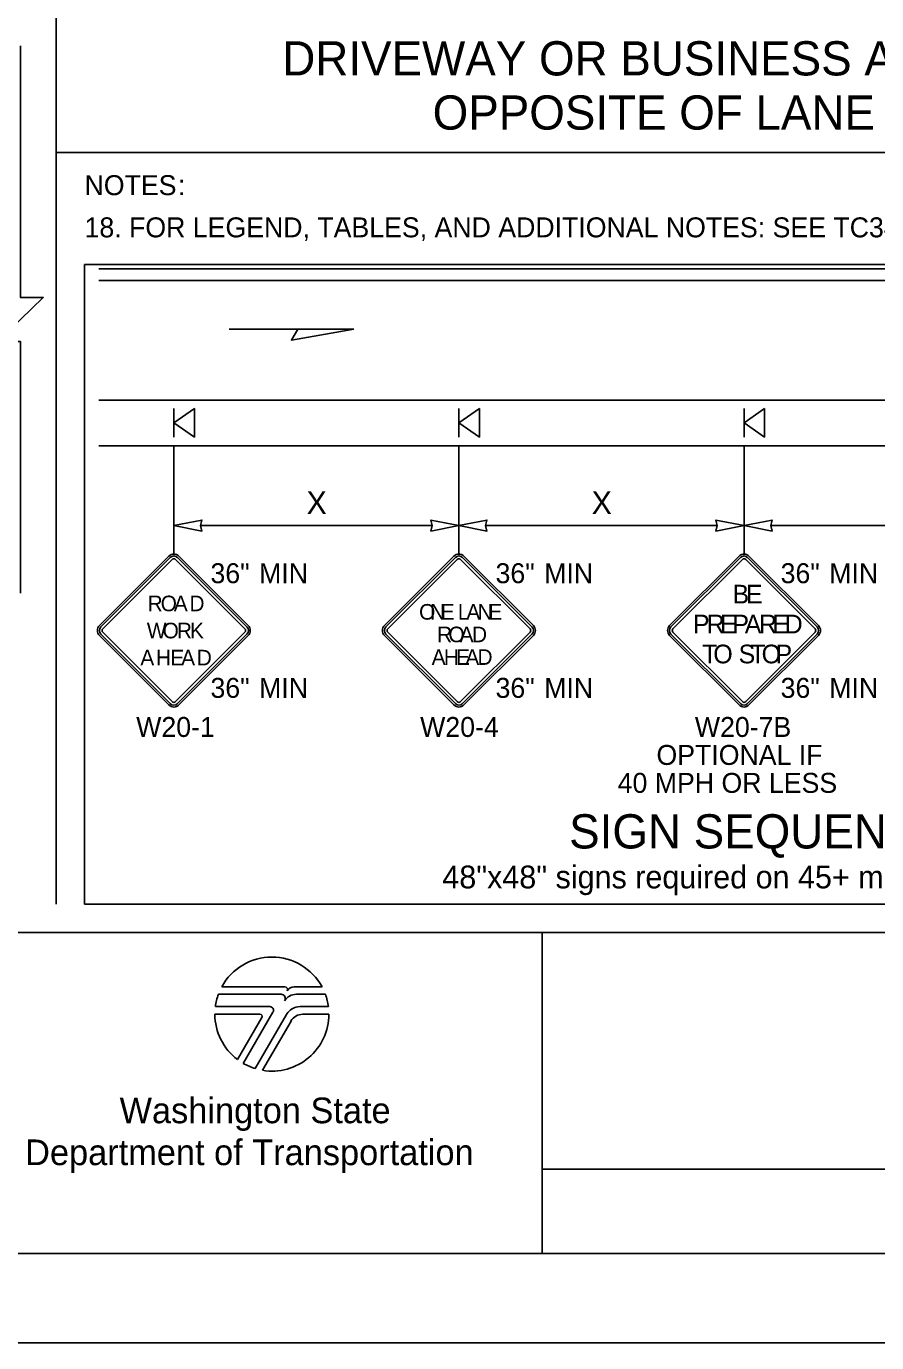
# Model space of a CAD drawing. Extents: x 99979.8 to 100075.7, y 99995 to 100010.7.
# Drawn here: x 100050.396 to 100053.379, y 99999.687 to 100004.304 of the extents above; entities that cross this region are included whole.
import ezdxf

# ---------------------------------------------------------------- set-up
doc = ezdxf.new("R2010")
doc.units = 0
for name, color, linetype in [('RD_ED_ShoulderPavedEdge', 7, 'Continuous'), ('RD_MK_LineDblYellowCenter', 7, 'Continuous'), ('RD_MK_LineEdgeWhite', 7, 'Continuous'), ('SH_DE_DetailHeading2Text', 7, 'Continuous'), ('SH_GI_GeneralNotesBodyText', 7, 'Continuous'), ('SH_GI_PlotLimits', 7, 'Continuous'), ('SH_GI_SheetBorder', 7, 'Continuous'), ('SH_GI_SheetTextInCells', 7, 'Continuous'), ('SH_GI_WSDOTLogo', 7, 'Continuous'), ('TR_SN_ConstructionSigns', 7, 'Continuous'), ('TR_WZ_PortableSignMountBlk-Org', 7, 'Continuous'), ('TR_WZ_WorkZoneDetails', 7, 'Continuous'), ('TR_WZ_WorkZoneTextCurrent', 7, 'Continuous')]:
    doc.layers.add(name, color=color, linetype=linetype)

msp = doc.modelspace()

# ---------------------------------------------------------------- linework, layer by layer
at = {"layer": 'RD_ED_ShoulderPavedEdge'}
msp.add_line((100050.65, 100002.8334), (100055.6, 100002.8334), dxfattribs=at)
at = {"layer": 'RD_MK_LineDblYellowCenter'}
for p, q in [((100050.65, 100003.4534), (100054.9276, 100003.4534)), ((100050.65, 100003.4134), (100054.9776, 100003.4134))]:
    msp.add_line(p, q, dxfattribs=at)
at = {"layer": 'RD_MK_LineEdgeWhite'}
msp.add_line((100050.65, 100002.9934), (100054.9776, 100002.9934), dxfattribs=at)
at = {"layer": 'SH_GI_PlotLimits'}
msp.add_lwpolyline([(100039.0625, 99999.6875), (100056.0625, 99999.6875), (100056.0625, 100010.6875), (100039.0625, 100010.6875)], close=True, dxfattribs=at)
at = {"layer": 'SH_GI_SheetBorder'}
for p, q in [((100040, 100001.1259), (100055.75, 100001.1259)), ((100052.2055, 100001.1259), (100052.2055, 100000)), ((100052.2055, 100000.2955), (100055.2079, 100000.2955)), ((100040, 100000), (100055.75, 100000))]:
    msp.add_line(p, q, dxfattribs=at)
at = {"layer": 'SH_GI_WSDOTLogo'}
for p, q in [((100051.303, 100000.9354), (100051.0815, 100000.9354)), ((100051.433, 100000.9354), (100051.3351, 100000.9354)), ((100051.2894, 100000.9094), (100051.0697, 100000.9094)), ((100051.343, 100000.9094), (100051.3429, 100000.9094)), ((100051.4448, 100000.9094), (100051.343, 100000.9094)), ((100051.0572, 100000.84), (100051.2148, 100000.84)), ((100051.059, 100000.8661), (100051.2496, 100000.8661)), ((100051.222, 100000.8277), (100051.1364, 100000.6807)), ((100051.261, 100000.8464), (100051.1567, 100000.6672)), ((100051.1989, 100000.6487), (100051.3089, 100000.839)), ((100051.3558, 100000.8661), (100051.4555, 100000.8661)), ((100051.3655, 100000.8394), (100051.4572, 100000.8394)), ((100051.2244, 100000.6428), (100051.3242, 100000.8156))]:
    msp.add_line(p, q, dxfattribs=at)
for centre, radius, start, end in [((100051.2572, 100000.84), 0.2, 28.4787, 151.532), ((100051.303, 100000.9263), 0.00903, 329.8742, 90.0033), ((100051.3352, 100000.9066), 0.0287, 90.0072, 148.1676), ((100051.2572, 100000.84), 0.2, 159.696, 172.5057), ((100051.2894, 100000.8946), 0.0148, 327.8418, 89.9985), ((100051.3429, 100000.861), 0.0484, 89.9953, 147.8238), ((100051.2572, 100000.84), 0.2, 7.4943, 20.2941), ((100051.2572, 100000.84), 0.2, 179.9986, 232.8433), ((100051.2149, 100000.8318), 0.0082, 329.7436, 90), ((100051.2572, 100000.84), 0.2, 260.5455, 359.8086), ((100051.2497, 100000.853), 0.0131, 329.7683, 90), ((100051.3558, 100000.8119), 0.0542, 90, 149.9974), ((100051.3654, 100000.7918), 0.0476, 90, 150.0543), ((100051.2572, 100000.84), 0.2, 239.7929, 253.0448)]:
    msp.add_arc(centre, radius, start, end, dxfattribs=at)
at = {"layer": 'TR_SN_ConstructionSigns'}
for p, q in [((100050.8959, 100002.4462), (100050.6523, 100002.2026)), ((100050.6523, 100002.2026), (100050.8959, 100002.4462)), ((100050.9007, 100002.4413), (100050.6571, 100002.1977)), ((100051.1695, 100002.1977), (100050.9258, 100002.4413)), ((100051.1743, 100002.2026), (100050.9307, 100002.4462)), ((100050.9307, 100002.4462), (100051.1743, 100002.2026)), ((100051.8959, 100002.4462), (100051.6523, 100002.2026)), ((100051.6523, 100002.2026), (100051.8959, 100002.4462)), ((100051.9007, 100002.4413), (100051.6571, 100002.1977)), ((100052.1695, 100002.1977), (100051.9258, 100002.4413)), ((100052.1743, 100002.2026), (100051.9307, 100002.4462)), ((100051.9307, 100002.4462), (100052.1743, 100002.2026)), ((100052.8959, 100002.4462), (100052.6523, 100002.2026)), ((100052.6523, 100002.2026), (100052.8959, 100002.4462)), ((100052.9007, 100002.4413), (100052.6571, 100002.1977)), ((100053.1695, 100002.1977), (100052.9258, 100002.4413)), ((100053.1743, 100002.2026), (100052.9307, 100002.4462)), ((100052.9307, 100002.4462), (100053.1743, 100002.2026)), ((100050.6639, 100002.191), (100050.9075, 100002.4346)), ((100050.9191, 100002.4346), (100051.1627, 100002.191)), ((100051.6639, 100002.191), (100051.9075, 100002.4346)), ((100051.9191, 100002.4346), (100052.1627, 100002.191)), ((100052.6639, 100002.191), (100052.9075, 100002.4346)), ((100052.9191, 100002.4346), (100053.1627, 100002.191)), ((100050.6523, 100002.1678), (100050.8959, 100001.9241)), ((100050.8959, 100001.9241), (100050.6523, 100002.1678)), ((100050.6571, 100002.1726), (100050.9007, 100001.929)), ((100050.9075, 100001.9357), (100050.6639, 100002.1794)), ((100051.1627, 100002.1794), (100050.9191, 100001.9357)), ((100050.9258, 100001.929), (100051.1695, 100002.1726)), ((100050.9307, 100001.9241), (100051.1743, 100002.1678)), ((100051.1743, 100002.1678), (100050.9307, 100001.9241)), ((100051.6523, 100002.1678), (100051.8959, 100001.9241)), ((100051.8959, 100001.9241), (100051.6523, 100002.1678)), ((100051.6571, 100002.1726), (100051.9007, 100001.929)), ((100051.9075, 100001.9357), (100051.6639, 100002.1794)), ((100052.1627, 100002.1794), (100051.9191, 100001.9357)), ((100051.9258, 100001.929), (100052.1695, 100002.1726)), ((100051.9307, 100001.9241), (100052.1743, 100002.1678)), ((100052.1743, 100002.1678), (100051.9307, 100001.9241)), ((100052.6523, 100002.1678), (100052.8959, 100001.9241)), ((100052.8959, 100001.9241), (100052.6523, 100002.1678)), ((100052.6571, 100002.1726), (100052.9007, 100001.929)), ((100052.9075, 100001.9357), (100052.6639, 100002.1794)), ((100053.1627, 100002.1794), (100052.9191, 100001.9357)), ((100052.9258, 100001.929), (100053.1695, 100002.1726)), ((100052.9307, 100001.9241), (100053.1743, 100002.1678)), ((100053.1743, 100002.1678), (100052.9307, 100001.9241))]:
    msp.add_line(p, q, dxfattribs=at)
for centre, radius, start, end in [((100050.9133, 100002.4288), 0.0246, 45, 135), ((100050.9133, 100002.4288), 0.0246, 45, 135), ((100050.9133, 100002.4288), 0.0178, 45, 135), ((100051.9133, 100002.4288), 0.0246, 45, 135), ((100051.9133, 100002.4288), 0.0246, 45, 135), ((100051.9133, 100002.4288), 0.0178, 45, 135), ((100052.9133, 100002.4288), 0.0246, 45, 135), ((100052.9133, 100002.4288), 0.0246, 45, 135), ((100052.9133, 100002.4288), 0.0178, 45, 135), ((100050.9133, 100002.4288), 0.0082, 45, 135), ((100051.9133, 100002.4288), 0.0082, 45, 135), ((100052.9133, 100002.4288), 0.0082, 45, 135), ((100050.6697, 100002.1852), 0.0246, 135, 225), ((100050.6697, 100002.1852), 0.0246, 135, 225), ((100050.6697, 100002.1852), 0.0178, 135, 225), ((100050.6697, 100002.1852), 0.0082, 135, 225), ((100051.1569, 100002.1852), 0.0082, 315, 45), ((100051.1569, 100002.1852), 0.0178, 315, 45), ((100051.1569, 100002.1852), 0.0246, 315, 45), ((100051.1569, 100002.1852), 0.0246, 315, 45), ((100051.6697, 100002.1852), 0.0246, 135, 225), ((100051.6697, 100002.1852), 0.0246, 135, 225), ((100051.6697, 100002.1852), 0.0178, 135, 225), ((100051.6697, 100002.1852), 0.0082, 135, 225), ((100052.1569, 100002.1852), 0.0082, 315, 45), ((100052.1569, 100002.1852), 0.0178, 315, 45), ((100052.1569, 100002.1852), 0.0246, 315, 45), ((100052.1569, 100002.1852), 0.0246, 315, 45), ((100052.6697, 100002.1852), 0.0246, 135, 225), ((100052.6697, 100002.1852), 0.0246, 135, 225), ((100052.6697, 100002.1852), 0.0178, 135, 225), ((100052.6697, 100002.1852), 0.0082, 135, 225), ((100053.1569, 100002.1852), 0.0082, 315, 45), ((100053.1569, 100002.1852), 0.0178, 315, 45), ((100053.1569, 100002.1852), 0.0246, 315, 45), ((100053.1569, 100002.1852), 0.0246, 315, 45), ((100050.9133, 100001.9415), 0.0082, 225, 315), ((100051.9133, 100001.9415), 0.0082, 225, 315), ((100052.9133, 100001.9415), 0.0082, 225, 315), ((100050.9133, 100001.9415), 0.0246, 225, 315), ((100050.9133, 100001.9415), 0.0246, 225, 315), ((100050.9133, 100001.9415), 0.0178, 225, 315), ((100051.9133, 100001.9415), 0.0246, 225, 315), ((100051.9133, 100001.9415), 0.0246, 225, 315), ((100051.9133, 100001.9415), 0.0178, 225, 315), ((100052.9133, 100001.9415), 0.0246, 225, 315), ((100052.9133, 100001.9415), 0.0246, 225, 315), ((100052.9133, 100001.9415), 0.0178, 225, 315)]:
    msp.add_arc(centre, radius, start, end, dxfattribs=at)
at = {"layer": 'TR_WZ_PortableSignMountBlk-Org'}
for p, q in [((100050.9133, 100002.8634), (100050.9133, 100002.9634)), ((100051.9133, 100002.8634), (100051.9133, 100002.9634)), ((100052.9133, 100002.8634), (100052.9133, 100002.9634))]:
    msp.add_line(p, q, dxfattribs=at)
for points in [[(100050.9133, 100002.9133), (100050.9851, 100002.9634), (100050.9851, 100002.8634)], [(100051.9133, 100002.9133), (100051.9851, 100002.9634), (100051.9851, 100002.8634)], [(100052.9133, 100002.9133), (100052.9851, 100002.9634), (100052.9851, 100002.8634)]]:
    msp.add_lwpolyline(points, close=True, dxfattribs=at)
at = {"layer": 'TR_WZ_WorkZoneDetails'}
for p, q in [((100050.5, 100010.275), (100050.5, 100001.2259)), ((100055.75, 100003.862), (100050.5, 100003.862)), ((100051.3482, 100003.2427), (100051.1071, 100003.2427)), ((100050.9133, 100002.8334), (100050.9133, 100002.4534)), ((100051.9133, 100002.8334), (100051.9133, 100002.4534)), ((100052.9133, 100002.8334), (100052.9133, 100002.4534)), ((100051.8195, 100002.5534), (100051.007, 100002.5534)), ((100052.8195, 100002.5534), (100052.007, 100002.5534)), ((100053.8195, 100002.5534), (100053.007, 100002.5534))]:
    msp.add_line(p, q, dxfattribs=at)
msp.add_lwpolyline([(100050.375, 100002.3159), (100050.375, 100003.1985), (100050.295, 100003.1985), (100050.455, 100003.3533), (100050.375, 100003.3533), (100050.375, 100004.2359)], dxfattribs=at)
for points in [[(100051.5447, 100003.2427), (100051.3259, 100003.2041), (100051.3482, 100003.2427)], [(100050.9133, 100002.5534), (100051.0116, 100002.5727), (100051.007, 100002.5534), (100051.0116, 100002.5341)], [(100051.9133, 100002.5534), (100051.815, 100002.5727), (100051.8195, 100002.5534), (100051.815, 100002.5341)], [(100051.9133, 100002.5534), (100052.0116, 100002.5727), (100052.007, 100002.5534), (100052.0116, 100002.5341)], [(100052.9133, 100002.5534), (100052.815, 100002.5727), (100052.8195, 100002.5534), (100052.815, 100002.5341)], [(100052.9133, 100002.5534), (100053.0116, 100002.5727), (100053.007, 100002.5534), (100053.0116, 100002.5341)]]:
    msp.add_lwpolyline(points, close=True, dxfattribs=at)
at = {"layer": 'TR_WZ_WorkZoneTextCurrent'}
msp.add_lwpolyline([(100050.6, 100003.4685), (100055.65, 100003.4685), (100055.65, 100001.2259), (100050.6, 100001.2259)], close=True, dxfattribs=at)

# ---------------------------------------------------------------- texts
at = {"layer": 'SH_DE_DetailHeading2Text'}
for s, p in [('DRIVEWAY OR BUSINESS ACCESS DETAIL', (100051.2936, 100004.132)), ('OPPOSITE OF LANE CLOSURE', (100051.8211, 100003.942)), ('SIGN SEQUENCE A', (100052.2998, 100001.4208))]:
    msp.add_text(s, height=0.12, rotation=360, dxfattribs=at).set_placement(p)
at = {"layer": 'SH_GI_GeneralNotesBodyText'}
for s, p in [('NOTES', (100050.6, 100003.7122)), (':', (100050.9275, 100003.7122)), ('18. FOR LEGEND, TABLES, AND ADDITIONAL NOTES: SEE TC347, SHEETS 4 & 5.', (100050.6, 100003.5642))]:
    msp.add_text(s, height=0.07, rotation=360, dxfattribs=at).set_placement(p)
at = {"layer": 'SH_GI_SheetTextInCells'}
for s, p in [('Washington State', (100050.7229, 100000.4571)), ('Department of Transportation', (100050.3916, 100000.3101))]:
    msp.add_text(s, height=0.090072, dxfattribs=at).set_placement(p)
at = {"layer": 'TR_SN_ConstructionSigns'}
for s, p in [('36"', (100051.0417, 100002.3512)), ('MIN', (100051.2123, 100002.3512)), ('36"', (100052.0417, 100002.3512)), ('MIN', (100052.2123, 100002.3512)), ('36"', (100053.0417, 100002.3512)), ('MIN', (100053.2123, 100002.3512)), ('36"', (100051.0417, 100001.9491)), ('MIN', (100051.2123, 100001.9491)), ('36"', (100052.0417, 100001.9491)), ('MIN', (100052.2123, 100001.9491)), ('36"', (100053.0417, 100001.9491)), ('MIN', (100053.2123, 100001.9491)), ('W20-1', (100050.7812, 100001.8119)), ('W20-4', (100051.7772, 100001.8119)), ('W20-7B', (100052.7409, 100001.8119)), ('OPTIONAL IF', (100052.6062, 100001.7139)), ('40 MPH OR LESS', (100052.4701, 100001.6159))]:
    msp.add_text(s, height=0.07, rotation=360, dxfattribs=at).set_placement(p)
for s, height, p in [('R', 0.0547, (100050.8213, 100002.2528)), ('O', 0.0547, (100050.867, 100002.2528)), ('A', 0.0547, (100050.9131, 100002.2528)), ('D', 0.0547, (100050.968, 100002.2528)), ('B', 0.0656, (100052.8728, 100002.2801)), ('E', 0.0656, (100052.9203, 100002.2801)), ('O', 0.0547, (100051.7735, 100002.2234)), ('N', 0.0547, (100051.8121, 100002.2234)), ('E', 0.0547, (100051.8497, 100002.2234)), ('L', 0.0547, (100051.9094, 100002.2234)), ('A', 0.0547, (100051.9392, 100002.2234)), ('N', 0.0547, (100051.9787, 100002.2234)), ('E', 0.0547, (100052.0163, 100002.2234)), ('W', 0.0547, (100050.8185, 100002.1578)), ('O', 0.0547, (100050.8738, 100002.1578)), ('R', 0.0547, (100050.9239, 100002.1578)), ('K', 0.0547, (100050.9698, 100002.1578)), ('P', 0.0656, (100052.734, 100002.1751)), ('R', 0.0656, (100052.7823, 100002.1751)), ('E', 0.0656, (100052.8289, 100002.1751)), ('P', 0.0656, (100052.8722, 100002.1751)), ('A', 0.0656, (100052.9159, 100002.1751)), ('R', 0.0656, (100052.9659, 100002.1751)), ('E', 0.0656, (100053.0125, 100002.1751)), ('D', 0.0656, (100053.0558, 100002.1751)), ('R', 0.0547, (100051.8367, 100002.1441)), ('O', 0.0547, (100051.8763, 100002.1441)), ('A', 0.0547, (100051.9158, 100002.1441)), ('D', 0.0547, (100051.9592, 100002.1441)), ('A', 0.0547, (100051.8176, 100002.0648)), ('H', 0.0547, (100051.8602, 100002.0648)), ('E', 0.0547, (100051.9029, 100002.0648)), ('A', 0.0547, (100051.9357, 100002.0648)), ('D', 0.0547, (100051.9784, 100002.0648)), ('T', 0.0656, (100052.7661, 100002.0701)), ('O', 0.0656, (100052.8055, 100002.0701)), ('S', 0.0656, (100052.8943, 100002.0701)), ('T', 0.0656, (100052.9355, 100002.0701)), ('O', 0.0656, (100052.975, 100002.0701)), ('P', 0.0656, (100053.0237, 100002.0701)), ('A', 0.0547, (100050.7957, 100002.0629)), ('H', 0.0547, (100050.8504, 100002.0629)), ('E', 0.0547, (100050.9007, 100002.0629)), ('A', 0.0547, (100050.939, 100002.0629)), ('D', 0.0547, (100050.9937, 100002.0629))]:
    msp.add_text(s, height=height, dxfattribs=at).set_placement(p)
at = {"layer": 'TR_WZ_WorkZoneTextCurrent'}
for p in [(100051.3786, 100002.5934), (100052.3786, 100002.5934)]:
    msp.add_text('X', height=0.08, rotation=360, dxfattribs=at).set_placement(p)
msp.add_text('48"x48" signs required on 45+ mph roadways', height=0.08, dxfattribs=at).set_placement((100051.8551, 100001.2808))

doc.saveas('drawing.dxf')
